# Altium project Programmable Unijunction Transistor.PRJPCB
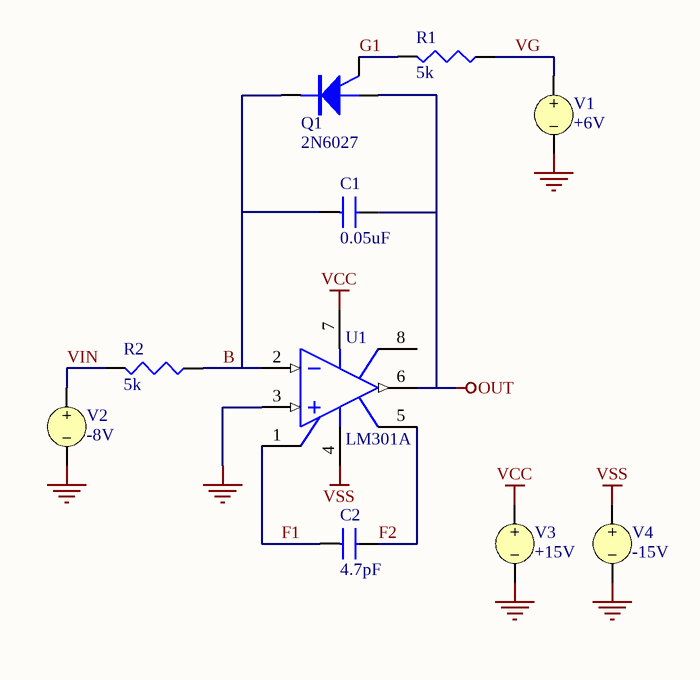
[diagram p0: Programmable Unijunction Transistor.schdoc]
1 sheet, 10 parts. Net scope: global (net labels, ports and power ports of the same name join across sheets).

## Sheet Programmable Unijunction Transistor.schdoc: Programmable UJT
size A4; Organization: Altium Limited; Address1: L3, 12a Rodborough Rd; Address2: Frenchs Forest; Address3: NSW; Address4: Australia 2086; DocumentNumber: 1; SheetNumber: 1; SheetTotal: 1

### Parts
C1  0.05uF
C2  4.7pF
Q1  2N6027
R1  5k
R2  5k
U1  LM301A
V1  +6V
V2  -8V
V3  +15V
V4  -15V

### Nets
GND: U1.3(IN+) V1.2 V2.2 V3.2 V4.2
OUT: C1.2 Q1.1(A) U1.6(OUT)
VCC: U1.7(VCC) V3.1
VSS: U1.4(VSS) V4.1
B: C1.1 Q1.3(K) R2.2(BOT) U1.2(IN-)
F1: C2.1 U1.1(N1/CMP)
F2: C2.2 U1.5(N2/CMP)
G1: Q1.2(G) R1.1(TOP)
VG: R1.2(BOT) V1.1
VIN: R2.1(TOP) V2.1

Not connected (* = marked no-connect by the designer): U1 8(FREQ_COMP)

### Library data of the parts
C1 C2 = CAP: Capacitor
Q1 = 2N6027: Programmable Unijunction Transistor
R1 R2 = RES: Resistor
U1 = LM301A: Operational Amplifier
V1-V4 = VSRC: Voltage Source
